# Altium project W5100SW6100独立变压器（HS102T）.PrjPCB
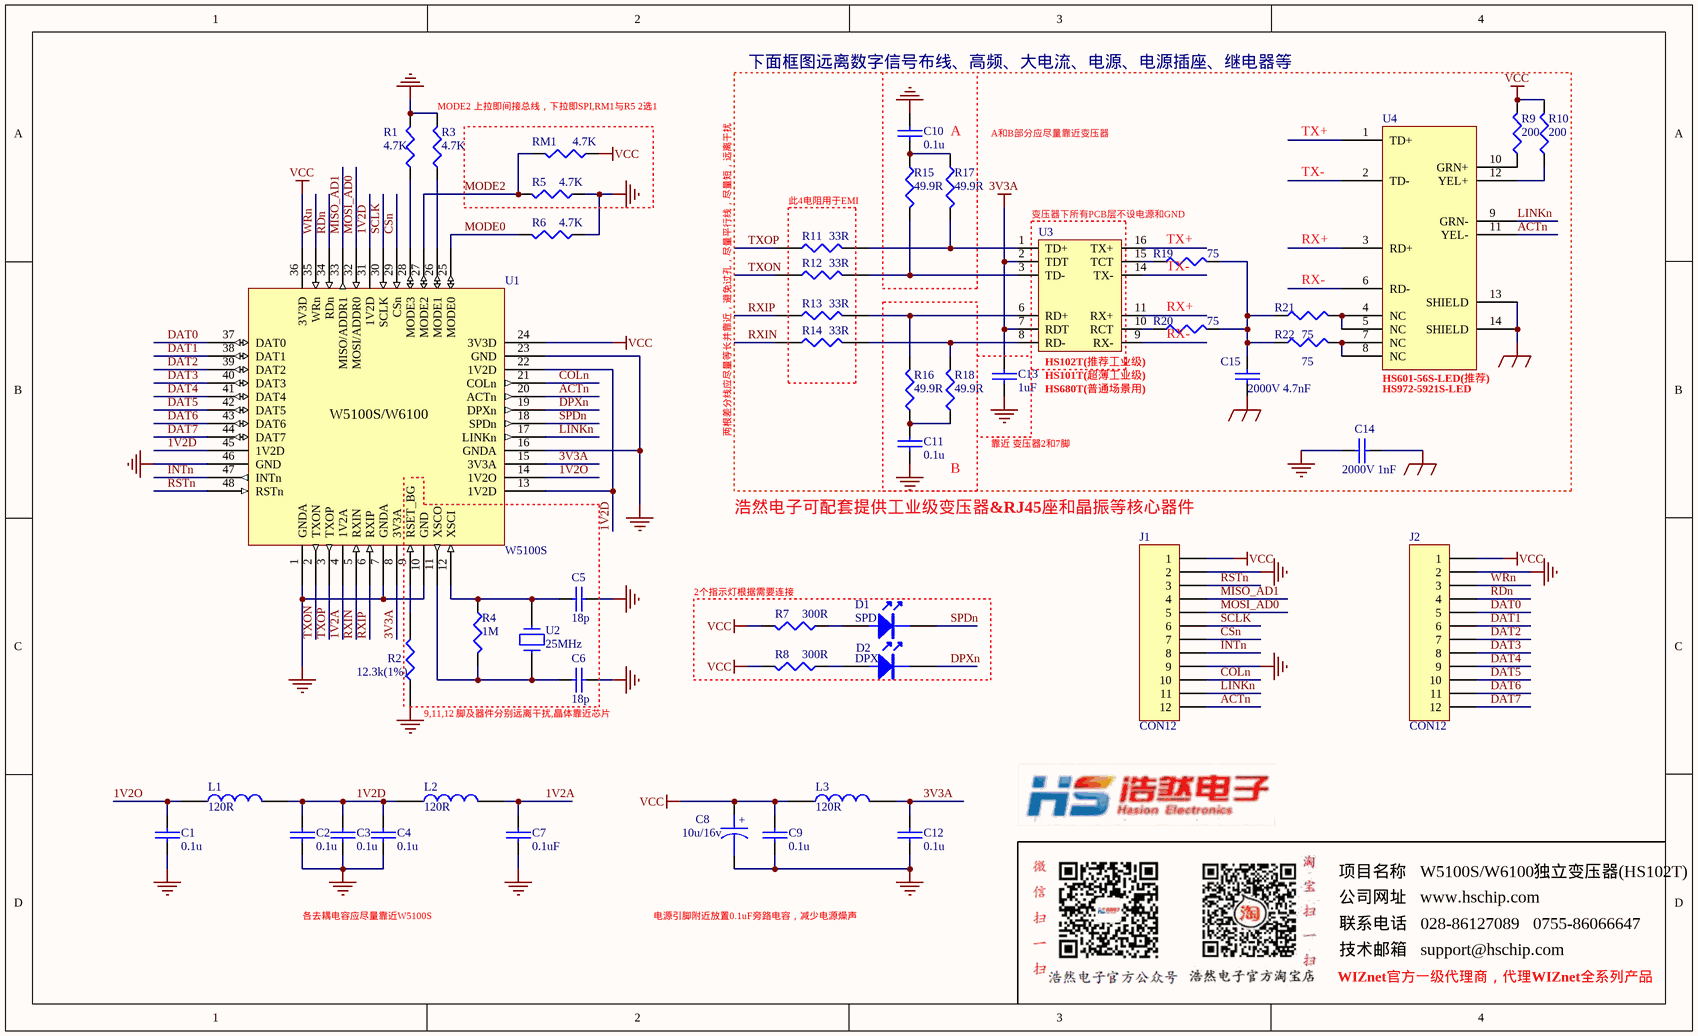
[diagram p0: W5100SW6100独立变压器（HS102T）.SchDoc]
1 sheet, 49 parts. Net scope: global (net labels, ports and power ports of the same name join across sheets).

## Sheet W5100SW6100独立变压器（HS102T）.SchDoc: W5100S独立变压器
size 317 x 193 mm; SheetNumber: 0; SheetTotal: 0; PageSetup: Record=PageOptions?CenterHorizontal=True?CenterVertical=True?PrintScale=0.92?XCorrection=1.00?YCorrection=1.00?PrintKind=0?BorderSize=5000000?LeftOffset=0?BottomOffset=0?Orientation=2?PaperLength=1000?PaperWidth=1000?Scale=100?PaperSource=7?PrintQuality=-4?MediaType=1?DitherType=10?PaperKind=A4?PrintScaleMode=1

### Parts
C1  0.1u  [0603]
C2  0.1u  [0603]
C3  0.1u  [0603]
C4  0.1u  [0603]
C5  18p  [0603]
C6  18p  [0603]
C7  0.1uF  [0603]
C8  10u/16v  [3216]
C9  0.1u  [0603]
C10  0.1u  [0603]
C11  0.1u  [0603]
C12  0.1u  [0603]
C13  1uF  [0603]
C14  2000V 1nF  [3216]
C15  2000V 4.7nF  [3216]
D1  SPD
D2  DPX
J1  CON12  [SIP12]
J2  CON12  [SIP12]
L1  120R  [0603]
L2  120R  [0603]
L3  120R  [0603]
R1  4.7K  [0603]
R2  12.3k(1%)  [0603]
R3  4.7K  [0603]
R4  1M  [0603]
R5  4.7K  [0603]
R6  4.7K  [0603]
R7  300R  [0603]
R8  300R  [0603]
R9  200  [0603]
R10  200  [0603]
R11  33R  [0603]
R12  33R  [0603]
R13  33R  [0603]
R14  33R  [0603]
R15  49.9R  [0603]
R16  49.9R  [0603]
R17  49.9R  [0603]
R18  49.9R  [0603]
R19  75  [0603]
R20  75  [0603]
R21  75  [0603]
R22  75  [0603]
RM1  4.7K  [0603]
U1  W5100S  [LQFP48-W5500/W5100S/W6100/C8T6]
U2  25MHz  [XTAL-49S]
U3  HS102T(推荐工业级)  [TR-HS101T/HS102T/HS680T]
U4  HS601-56S-LED(推荐)  [RJ45-HS601-56S-LED]

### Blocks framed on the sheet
下面框图远离数字信号布线、高频、大电流、电源、电源插座、继电器等: C10 C13-C15 R9 R10 R15 R17 R19-R22 U4
此4电阻用于EMI: R11-R14
变压器下所有PCB层不设电源和GND: U3
B: C11 R16 R18
2个指示灯根据需要连接: D1 D2 R7 R8

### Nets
3V3A: C12.1 C13.1 L3.2 U1.8(3V3A) U1.15(3V3A) U3.2(TDT) U3.7(RDT)
CGND: C14.2 C15.2 U4.13(SHIELD) U4.14(SHIELD)
GND: C1.2 C2.2 C3.2 C4.2 C5.2 C6.2 C7.1 C8.2 C9.2 C10.2 C11.2 C12.2 C13.2 C14.1 J1.2 J1.9 J2.2 R1.2 R2.1 R3.2 R5.1 R6.1 U1.1(GNDA) U1.7(GNDA) U1.10(GND) U1.16(GNDA) U1.23(GND) U1.46(GND)
VCC: C8.1 C9.1 J1.1 J2.1 L3.1 R7.2 R8.2 R9.2 R10.2 RM1.1 U1.24(3V3D) U1.36(3V3D)
1V2A: C7.2 L2.2 U1.4(1V2A)
1V2D: C2.1 C3.1 C4.1 L1.2 L2.1 U1.13(1V2D) U1.22(1V2D) U1.31(1V2D) U1.45(1V2D)
1V2O: C1.1 L1.1 U1.14(1V2O)
ACTn: J1.12 U1.20(ACTn) U4.11(YEL-)
COLn: J1.10 U1.21(COLn)
CSn: J1.7 U1.29(CSn)
DAT0: J2.5 U1.37(DAT0)
DAT1: J2.6 U1.38(DAT1)
DAT2: J2.7 U1.39(DAT2)
DAT3: J2.8 U1.40(DAT3)
DAT4: J2.9 U1.41(DAT4)
DAT5: J2.10 U1.42(DAT5)
DAT6: J2.11 U1.43(DAT6)
DAT7: J2.12 U1.44(DAT7)
DPXn: D2.K U1.19(DPXn)
INTn: J1.8 U1.47(INTn)
LINKn: J1.11 U1.17(LINKn) U4.9(GRN-)
MISO_AD1: J1.4 U1.33(MISO/ADDR1)
MODE0: R6.2 U1.25(MODE0)
MODE2: R5.2 RM1.2 U1.27(MODE2)
MOSI_AD0: J1.5 U1.32(MOSI/ADDR0)
RDn: J2.4 U1.34(RDn)
RSTn: J1.3 U1.48(RSTn)
RX+: U3.11(RX+) U4.3(RD+)
RX-: U3.9(RX-) U4.6(RD-)
RXIN: R14.1 U1.5(RXIN)
RXIP: R13.1 U1.6(RXIP)
SCLK: J1.6 U1.30(SCLK)
SPDn: D1.K U1.18(SPDn)
TX+: U3.16(TX+) U4.1(TD+)
TX-: U3.14(TX-) U4.2(TD-)
TXON: R12.1 U1.2(TXON)
TXOP: R11.1 U1.3(TXOP)
WRn: J2.3 U1.35(WRn)
NetC5_1: C5.1 R4.1 U1.12(XSCI) U2.2
NetC6_1: C6.1 R4.2 U1.11(XSCO) U2.1
NetC10_1: C10.1 R15.1 R17.1
NetC11_1: C11.1 R16.1 R18.1
NetC15_1: C15.1 R19.2 R20.2 R21.1 R22.1
NetD1_A: D1.A R7.1
NetD2_A: D2.A R8.1
NetR1_1: R1.1 U1.28(MODE3)
NetR2_2: R2.2 U1.9(RSET_BG)
NetR3_1: R3.1 U1.26(MODE1)
NetR9_1: R9.1 U4.10(GRN+)
NetR10_1: R10.1 U4.12(YEL+)
NetR11_2: R11.2 R17.2 U3.1(TD+)
NetR12_2: R12.2 R15.2 U3.3(TD-)
NetR13_2: R13.2 R16.2 U3.6(RD+)
NetR14_2: R14.2 R18.2 U3.8(RD-)
NetR19_1: R19.1 U3.15(TCT)
NetR20_1: R20.1 U3.10(RCT)
NetR21_2: R21.2 U4.4(NC) U4.5(NC)
NetR22_2: R22.2 U4.7(NC) U4.8(NC)

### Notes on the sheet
- (near R3) MODE2 上拉即间接总线，下拉即SPI,RM1与R5 2选1
- A
- (near R17) A和B部分应尽量靠近变压器
- HS101T(超薄工业级)
- (near U1) W5100S/W6100
- 两根差分线应尽量等长并靠近，避免过孔，尽量平行线，尽量短，远离干扰
- 靠近 变压器2和7脚
- HS680T(普通场景用)
- (near U4) HS972-5921S-LED
- 9,11,12 脚及器件分别远离干扰,晶体靠近芯片
- 各去耦电容应尽量靠近W5100S
- 电源引脚附近放置0.1uF旁路电容，减少电源燥声
- 公司网址   www.hschip.com
- 项目名称   W5100S/W6100独立变压器(HS102T)
- WIZnet官方一级代理商，代理WIZnet全系列产品
- 联系电话   028-86127089   0755-86066647
- 技术邮箱   support@hschip.com
- Labels drawn without touching a wire or pin: 浩然电子可配套提供工业级变压器&RJ45座和晶振等核心器件

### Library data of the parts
C1-C7 C9-C15 = CAP: Capacitor
C8 = CAPACITOR POL: Capacitor
D1 D2 = LED
J1 J2 = CON12: Connector
L1-L3 = INDUCTOR
R1-R22 RM1 = RES1
U2 = CRYSTAL
U3 = HS102T
U4 = HS601 /HS972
